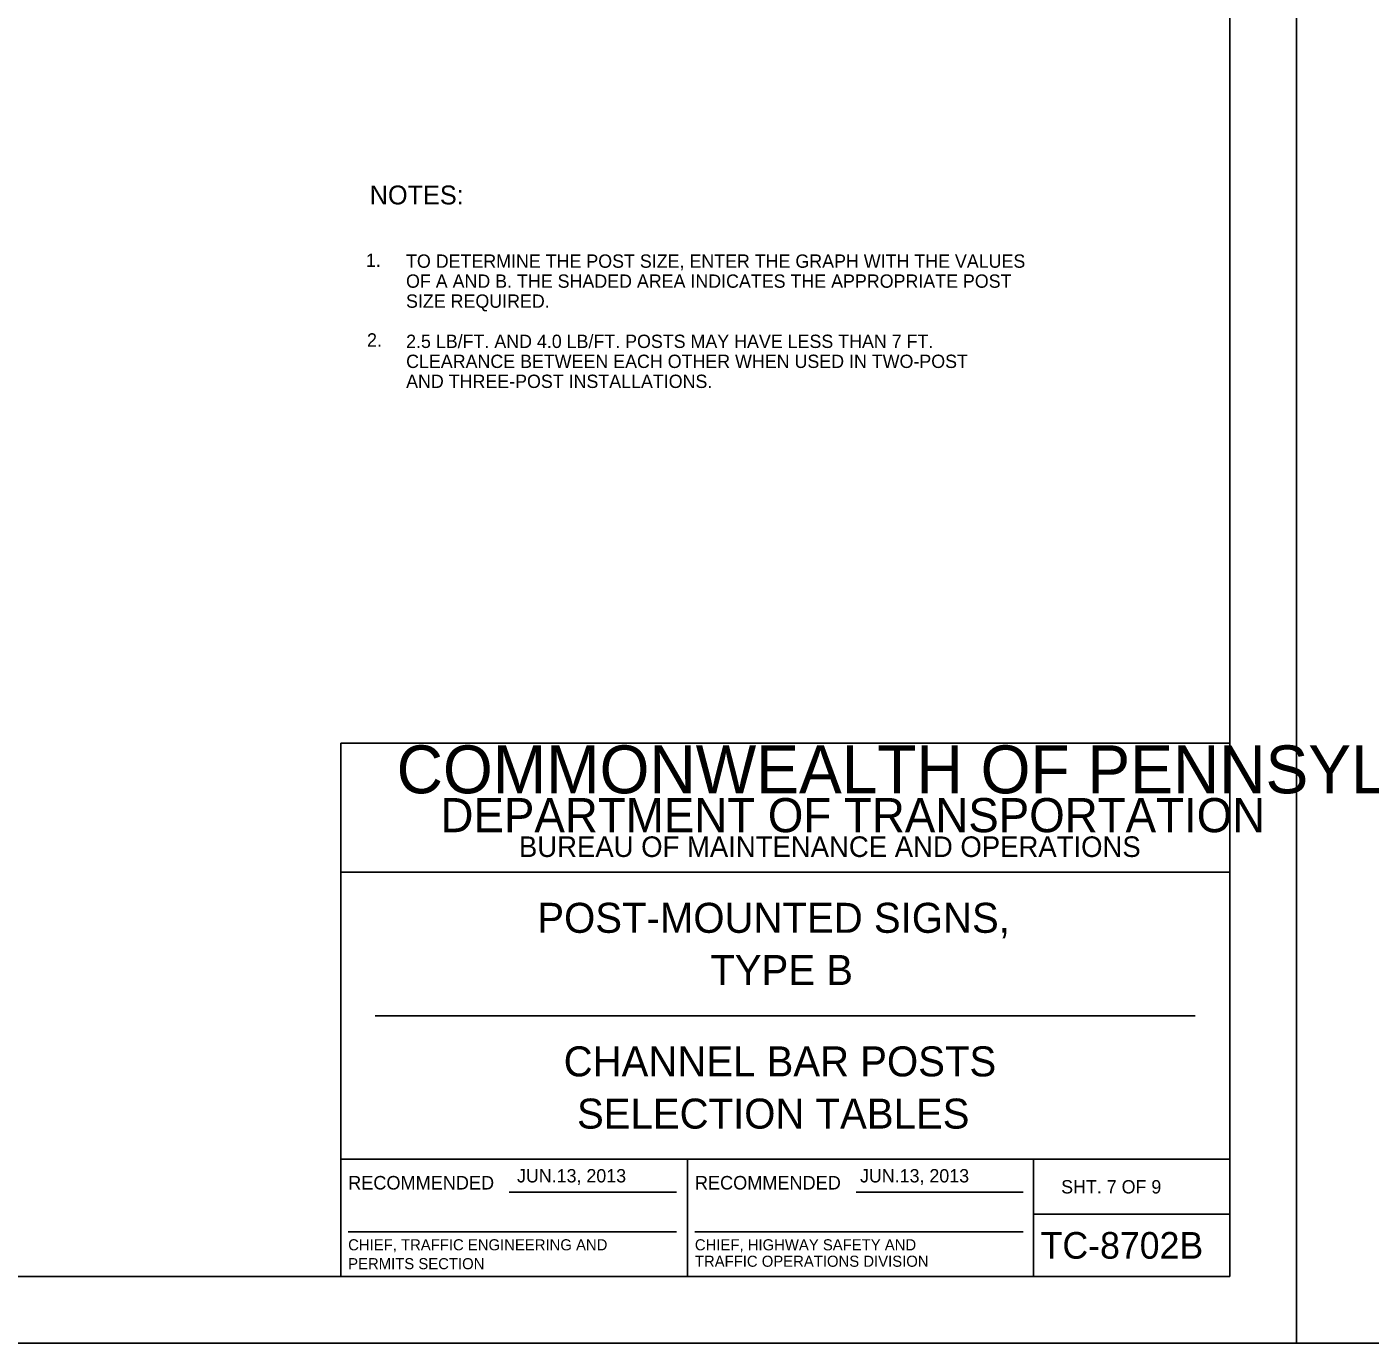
# Model space of a CAD drawing. Extents: x 644358 to 648627, y 294594 to 295782.
# Drawn here: x 645754.7 to 646056.9, y 294593.6 to 294889.9 of the extents above; entities that cross this region are included whole.
import ezdxf

# ---------------------------------------------------------------- set-up
doc = ezdxf.new("R2010")
doc.units = 0
for name, color, linetype in [('1', 7, 'Continuous'), ('2', 7, 'Continuous'), ('3', 7, 'Continuous'), ('4', 7, 'Continuous'), ('PLT-BNDY', 7, 'Continuous')]:
    doc.layers.add(name, color=color, linetype=linetype)

msp = doc.modelspace()

# ---------------------------------------------------------------- linework, layer by layer
at = {"layer": '1'}
for p, q in [((646025.31, 294608.63), (646025.31, 295172.63)), ((645825.31, 294608.63), (645825.31, 294728.63)), ((645825.31, 294728.63), (646025.31, 294728.63)), ((646025.31, 294699.63), (645825.31, 294699.63)), ((645833.06, 294667.31), (646017.56, 294667.31)), ((645825.31, 294635), (646025.31, 294635)), ((645903.31, 294635), (645903.31, 294608.63)), ((645981.19, 294608.63), (645981.19, 294635)), ((645863.24, 294627.57), (645900.87, 294627.57)), ((645941.24, 294627.57), (645978.87, 294627.57)), ((645981.19, 294622.63), (646025.31, 294622.63)), ((645826.99, 294618.68), (645900.87, 294618.68)), ((645904.99, 294618.68), (645978.87, 294618.68)), ((646025.31, 294608.63), (645239.31, 294608.63)), ((645239.31, 294608.63), (645825.31, 294608.63))]:
    msp.add_line(p, q, dxfattribs=at)
at = {"layer": 'PLT-BNDY'}
for points in [[(645199.31, 295187.63), (646040.31, 295187.63), (646040.31, 294593.63), (645199.31, 294593.63)], [(646040.31, 295187.63), (646881.31, 295187.63), (646881.31, 294593.63), (646040.31, 294593.63)]]:
    msp.add_lwpolyline(points, close=True, dxfattribs=at)

# ---------------------------------------------------------------- texts
at = {"layer": '1'}
for s, height, p in [('COMMONWEALTH OF PENNSYLVANIA', 10.7828, (645837.9, 294717.36)), ('DEPARTMENT OF TRANSPORTATION', 7.6837, (645847.76, 294708.61)), ('BUREAU OF MAINTENANCE AND OPERATIONS', 4.6253, (645865.41, 294703.04)), ('POST-MOUNTED SIGNS,', 6.75, (645869.54, 294685.97)), ('TYPE B', 6.75, (645908.45, 294674.22)), ('CHANNEL BAR POSTS', 6.75, (645875.47, 294653.66)), ('SELECTION TABLES', 6.75, (645878.47, 294641.91)), ('RECOMMENDED', 3.048, (645826.99, 294628.2)), ('RECOMMENDED', 3.048, (645904.99, 294628.2)), ('SHT. 7 OF 9', 3, (645987.39, 294627.31)), ('CHIEF, TRAFFIC ENGINEERING AND', 2.5, (645826.99, 294614.51)), ('CHIEF, HIGHWAY SAFETY AND', 2.5, (645904.99, 294614.51)), ('TC-8702B', 6, (645982.77, 294612.63)), ('TRAFFIC OPERATIONS DIVISION', 2.5, (645904.99, 294610.81)), ('PERMITS SECTION', 2.5, (645826.99, 294610.26))]:
    msp.add_text(s, height=height, dxfattribs=at).set_placement(p)
at = {"layer": '2'}
for p in [(645864.98, 294629.79), (645942.14, 294629.79)]:
    msp.add_text('JUN.13, 2013', height=3, dxfattribs=at).set_placement(p)
at = {"layer": '3'}
for s, p in [('1.', (645830.99, 294835.83)), ('TO DETERMINE THE POST SIZE, ENTER THE GRAPH WITH THE VALUES', (645840.01, 294835.63)), ('OF A AND B. THE SHADED AREA INDICATES THE APPROPRIATE POST', (645840.01, 294831.13)), ('SIZE REQUIRED.', (645840.01, 294826.63)), ('2.', (645831.24, 294817.89)), ('2.5 LB/FT. AND 4.0 LB/FT. POSTS MAY HAVE LESS THAN 7 FT.', (645840.03, 294817.58)), ('CLEARANCE BETWEEN EACH OTHER WHEN USED IN TWO-POST ', (645840.03, 294813.08)), ('AND THREE-POST INSTALLATIONS.', (645840.03, 294808.58))]:
    msp.add_text(s, height=3, dxfattribs=at).set_placement(p)
at = {"layer": '4'}
msp.add_text('NOTES:', height=4.25, dxfattribs=at).set_placement((645831.84, 294849.89))

doc.saveas('drawing.dxf')
